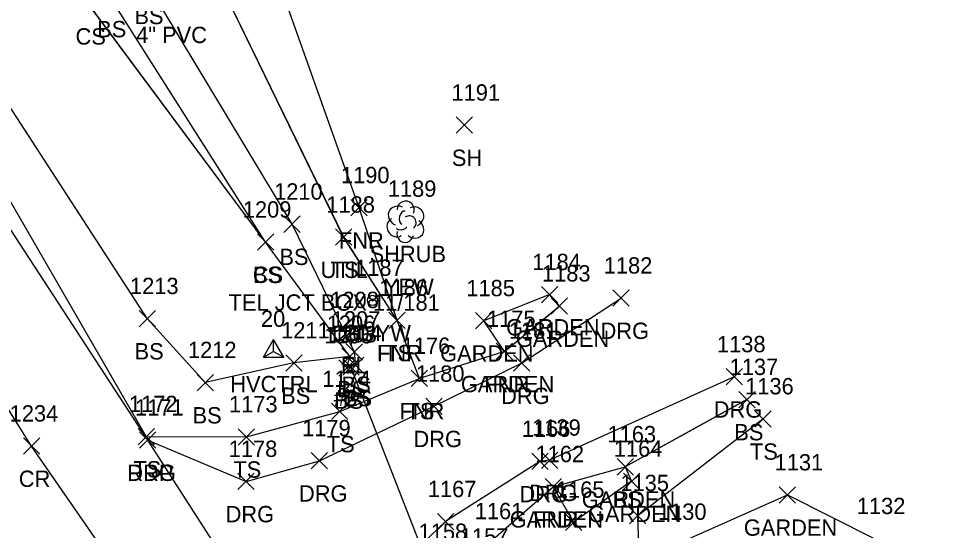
# Model space of a CAD drawing. Extents: x 1415642 to 1422021, y 544543 to 547232.
# Drawn here: x 1416447 to 1416560.6, y 546484.6 to 546547.3 of the extents above; entities that cross this region are included whole.
import ezdxf

# ---------------------------------------------------------------- set-up
doc = ezdxf.new("R2010")
doc.units = 0
for name, color, linetype in [('C_A', 7, 'Continuous'), ('C_I', 7, 'Continuous'), ('CPSM', 7, 'Continuous'), ('D_A', 7, 'Continuous'), ('D_C', 7, 'Continuous'), ('D_I', 7, 'Continuous'), ('D_TIC', 7, 'Continuous'), ('DCP', 7, 'Continuous'), ('L_A', 7, 'Continuous'), ('L_C', 7, 'Continuous'), ('L_I', 7, 'Continuous'), ('L_TIC', 7, 'Continuous'), ('LAPB', 7, 'Continuous'), ('LELB', 7, 'Continuous'), ('LFNC', 7, 'Continuous'), ('LSH', 7, 'Continuous'), ('P_A', 7, 'Continuous'), ('P_I', 7, 'Continuous'), ('P_TIC', 7, 'Continuous'), ('PET', 7, 'Continuous'), ('PRC', 7, 'Continuous'), ('R_A', 7, 'Continuous'), ('R_I', 7, 'Continuous'), ('R_TIC', 7, 'Continuous'), ('RDG', 7, 'Continuous'), ('U_A', 7, 'Continuous'), ('U_C', 7, 'Continuous'), ('U_I', 7, 'Continuous'), ('UDEFAULT', 7, 'Continuous'), ('UEPT', 7, 'Continuous'), ('UPGW', 7, 'Continuous')]:
    doc.layers.add(name, color=color, linetype=linetype)

msp = doc.modelspace()

# ---------------------------------------------------------------- linework, layer by layer
at = {"layer": 'CPSM'}
for p, q in [((1416476.98, 546505.82), (1416478.23, 546507.98)), ((1416479.48, 546505.82), (1416478.23, 546507.98)), ((1416478.23, 546506.54), (1416478.23, 546507.98)), ((1416476.98, 546505.82), (1416478.23, 546506.54)), ((1416478.23, 546506.54), (1416478.23, 546506.54)), ((1416478.23, 546506.54), (1416479.48, 546505.82)), ((1416476.98, 546505.82), (1416479.48, 546505.82))]:
    msp.add_line(p, q, dxfattribs=at)
at = {"layer": 'D_TIC'}
for points in [[(1416486.7, 546503.64), (1416488.7, 546505.64)], [(1416488.7, 546503.64), (1416486.7, 546505.64)]]:
    msp.add_lwpolyline(points, dxfattribs=at)
at = {"layer": 'DCP'}
msp.add_lwpolyline([(1416498.95, 546475.82), (1416487.7, 546504.64)], dxfattribs=at)
msp.add_lwpolyline([(1416498.95, 546475.82), (1416487.7, 546504.64)], dxfattribs=at)
at = {"layer": 'L_TIC'}
for points in [[(1416500.58, 546533.23), (1416502.58, 546535.23)], [(1416502.58, 546533.23), (1416500.58, 546535.23)], [(1416487.7, 546523.12), (1416489.7, 546525.12)], [(1416489.7, 546523.12), (1416487.7, 546525.12)], [(1416479.5, 546521.11), (1416481.5, 546523.11)], [(1416481.5, 546521.11), (1416479.5, 546523.11)], [(1416485.81, 546519.52), (1416487.81, 546521.52)], [(1416487.81, 546519.52), (1416485.81, 546521.52)], [(1416476.24, 546518.91), (1416478.24, 546520.91)], [(1416478.24, 546518.91), (1416476.24, 546520.91)], [(1416476.24, 546518.91), (1416478.24, 546520.91)], [(1416478.24, 546518.91), (1416476.24, 546520.91)], [(1416511.04, 546512.49), (1416513.04, 546514.49)], [(1416513.04, 546512.49), (1416511.04, 546514.49)], [(1416512.23, 546511.09), (1416514.23, 546513.09)], [(1416514.23, 546511.09), (1416512.23, 546513.09)], [(1416461.76, 546509.55), (1416463.76, 546511.55)], [(1416463.76, 546509.55), (1416461.76, 546511.55)], [(1416492.36, 546509.33), (1416494.36, 546511.33)], [(1416494.36, 546509.33), (1416492.36, 546511.33)], [(1416492.36, 546509.33), (1416494.36, 546511.33)], [(1416494.36, 546509.33), (1416492.36, 546511.33)], [(1416502.97, 546509.29), (1416504.97, 546511.29)], [(1416504.97, 546509.29), (1416502.97, 546511.29)], [(1416502.97, 546509.29), (1416504.97, 546511.29)], [(1416504.97, 546509.29), (1416502.97, 546511.29)], [(1416486.57, 546504.93), (1416488.57, 546506.93)], [(1416488.57, 546504.93), (1416486.57, 546506.93)], [(1416486.57, 546504.93), (1416488.57, 546506.93)], [(1416488.57, 546504.93), (1416486.57, 546506.93)], [(1416487.12, 546505.46), (1416489.12, 546507.46)], [(1416489.12, 546505.46), (1416487.12, 546507.46)], [(1416505.5, 546505.54), (1416507.5, 546507.54)], [(1416507.5, 546505.54), (1416505.5, 546507.54)], [(1416505.5, 546505.54), (1416507.5, 546507.54)], [(1416507.5, 546505.54), (1416505.5, 546507.54)], [(1416505.5, 546505.54), (1416507.5, 546507.54)], [(1416507.5, 546505.54), (1416505.5, 546507.54)], [(1416479.71, 546504.12), (1416481.71, 546506.12)], [(1416481.71, 546504.12), (1416479.71, 546506.12)], [(1416486.21, 546503.52), (1416488.21, 546505.52)], [(1416488.21, 546503.52), (1416486.21, 546505.52)], [(1416487.29, 546503.83), (1416489.29, 546505.83)], [(1416489.29, 546503.83), (1416487.29, 546505.83)], [(1416487.29, 546503.83), (1416489.29, 546505.83)], [(1416489.29, 546503.83), (1416487.29, 546505.83)], [(1416495.1, 546502.23), (1416497.1, 546504.23)], [(1416497.1, 546502.23), (1416495.1, 546504.23)], [(1416495.1, 546502.23), (1416497.1, 546504.23)], [(1416497.1, 546502.23), (1416495.1, 546504.23)], [(1416468.86, 546501.72), (1416470.86, 546503.72)], [(1416470.86, 546501.72), (1416468.86, 546503.72)], [(1416535.22, 546499.65), (1416537.22, 546501.65)], [(1416537.22, 546499.65), (1416535.22, 546501.65)], [(1416485.33, 546498.19), (1416487.33, 546500.19)], [(1416487.33, 546498.19), (1416485.33, 546500.19)], [(1416537.17, 546497.28), (1416539.17, 546499.28)], [(1416539.17, 546497.28), (1416537.17, 546499.28)], [(1416461.64, 546495.11), (1416463.64, 546497.11)], [(1416463.64, 546495.11), (1416461.64, 546497.11)], [(1416461.64, 546495.11), (1416463.64, 546497.11)], [(1416463.64, 546495.11), (1416461.64, 546497.11)], [(1416473.89, 546495.08), (1416475.89, 546497.08)], [(1416475.89, 546495.08), (1416473.89, 546497.08)], [(1416520.31, 546491.41), (1416522.31, 546493.41)], [(1416522.31, 546491.41), (1416520.31, 546493.41)], [(1416520.31, 546491.41), (1416522.31, 546493.41)], [(1416522.31, 546491.41), (1416520.31, 546493.41)], [(1416511.48, 546488.98), (1416513.48, 546490.98)], [(1416513.48, 546488.98), (1416511.48, 546490.98)], [(1416511.48, 546488.98), (1416513.48, 546490.98)], [(1416513.48, 546488.98), (1416511.48, 546490.98)], [(1416511.48, 546488.98), (1416513.48, 546490.98)], [(1416513.48, 546488.98), (1416511.48, 546490.98)], [(1416521.07, 546489.64), (1416523.07, 546491.64)], [(1416523.07, 546489.64), (1416521.07, 546491.64)], [(1416540.16, 546487.97), (1416542.16, 546489.97)], [(1416542.16, 546487.97), (1416540.16, 546489.97)], [(1416521.83, 546485.44), (1416523.83, 546487.44)], [(1416523.83, 546485.44), (1416521.83, 546487.44)], [(1416513.98, 546484.63), (1416515.98, 546486.63)], [(1416515.98, 546484.63), (1416513.98, 546486.63)], [(1416513.98, 546484.63), (1416515.98, 546486.63)], [(1416515.98, 546484.63), (1416513.98, 546486.63)]]:
    msp.add_lwpolyline(points, dxfattribs=at)
at = {"layer": 'LAPB'}
for points in [[(1416506.5, 546506.54), (1416513.23, 546512.09), (1416512.04, 546513.49), (1416503.97, 546510.29)], [(1416506.5, 546506.54), (1416513.22, 546512.09), (1416512.04, 546513.49), (1416503.97, 546510.29)], [(1416506.5, 546506.54), (1416503.97, 546510.29)], [(1416506.5, 546506.54), (1416503.97, 546510.29)], [(1416512.48, 546489.98), (1416521.31, 546492.41), (1416522.07, 546490.64), (1416514.98, 546485.63)], [(1416512.48, 546489.98), (1416521.31, 546492.41), (1416522.07, 546490.65), (1416514.98, 546485.63)], [(1416512.48, 546489.98), (1416514.98, 546485.63)], [(1416512.48, 546489.98), (1416514.98, 546485.63)], [(1416543.7, 546466.42), (1416530.22, 546473.8), (1416527.52, 546482.92), (1416541.16, 546488.97), (1416551.79, 546483.62)], [(1416543.71, 546466.42), (1416530.22, 546473.8), (1416527.52, 546482.91), (1416541.17, 546488.97), (1416551.8, 546483.62)]]:
    msp.add_lwpolyline(points, dxfattribs=at)
at = {"layer": 'LELB'}
for points in [[(1416487.57, 546505.93), (1416480.71, 546505.12), (1416469.86, 546502.72), (1416462.76, 546510.55), (1416442.83, 546541.19), (1416430.44, 546560.72), (1416424.35, 546585.18), (1416398.34, 546624.28), (1416389.66, 546643.26), (1416377.3, 546653.03), (1416344.54, 546704.05), (1416343.42, 546724.77), (1416329.35, 546768.04), (1416303.68, 546799.52), (1416274.8, 546819.39), (1416239.26, 546839.41), (1416210.61, 546845.46), (1416203.47, 546849.21), (1416195, 546854.49)], [(1416487.57, 546505.93), (1416480.71, 546505.12), (1416469.86, 546502.72), (1416462.76, 546510.55), (1416442.83, 546541.19), (1416430.44, 546560.72), (1416424.35, 546585.18), (1416398.34, 546624.28), (1416389.66, 546643.27), (1416377.3, 546653.03), (1416344.54, 546704.05), (1416343.42, 546724.76), (1416329.35, 546768.04), (1416303.68, 546799.52), (1416274.8, 546819.4), (1416239.26, 546839.41), (1416210.61, 546845.46), (1416203.48, 546849.21), (1416195, 546854.49)], [(1416488.29, 546504.83), (1416488.12, 546506.46), (1416480.5, 546522.11), (1416462.74, 546551.59), (1416447.84, 546594.51), (1416422.44, 546641.16), (1416410.18, 546676.27), (1416393.07, 546713.79), (1416378.8, 546749.63), (1416367.97, 546783.97), (1416347.35, 546811.63), (1416340.26, 546839.45), (1416338.76, 546849.28)], [(1416488.29, 546504.83), (1416488.12, 546506.46), (1416480.5, 546522.11), (1416462.74, 546551.59), (1416447.84, 546594.51), (1416422.44, 546641.16), (1416410.17, 546676.27), (1416393.07, 546713.79), (1416378.8, 546749.63), (1416367.97, 546783.97), (1416347.34, 546811.63), (1416340.26, 546839.45), (1416338.76, 546849.28)], [(1416462.64, 546496.11), (1416437.87, 546538.89), (1416411.19, 546576.82), (1416382.17, 546614.17), (1416360.8, 546639.39), (1416323.65, 546683.15), (1416301.53, 546707.03), (1416273.6, 546735.69), (1416258.67, 546751.22), (1416224.41, 546784.74), (1416201.13, 546806.07), (1416169.09, 546832.26)], [(1416462.64, 546496.11), (1416437.87, 546538.89), (1416411.18, 546576.82), (1416382.17, 546614.17), (1416360.8, 546639.39), (1416323.65, 546683.15), (1416301.53, 546707.03), (1416273.6, 546735.69), (1416258.67, 546751.22), (1416224.4, 546784.74), (1416201.13, 546806.07), (1416169.09, 546832.26)], [(1416488.29, 546504.83), (1416487.21, 546504.52), (1416487.57, 546505.93), (1416477.24, 546519.91), (1416458.18, 546549.98), (1416444.98, 546593.05), (1416421.02, 546640.5), (1416406.73, 546674.57), (1416393.07, 546713.79)], [(1416488.29, 546504.83), (1416487.21, 546504.52), (1416487.57, 546505.93), (1416477.24, 546519.91), (1416458.18, 546549.99), (1416444.98, 546593.04), (1416421.01, 546640.5), (1416406.73, 546674.57), (1416393.07, 546713.79)], [(1416493.36, 546510.33), (1416486.81, 546520.52), (1416469.71, 546555.6), (1416453.47, 546601.16)], [(1416493.36, 546510.33), (1416486.82, 546520.52), (1416469.71, 546555.59), (1416453.47, 546601.16)], [(1416477.24, 546519.91), (1416455.53, 546549.09), (1416441.96, 546593.48)], [(1416477.24, 546519.91), (1416455.53, 546549.1), (1416441.96, 546593.48)], [(1416462.64, 546496.11), (1416474.89, 546496.08), (1416486.33, 546499.19), (1416496.1, 546503.23)], [(1416462.64, 546496.11), (1416474.89, 546496.08), (1416486.33, 546499.19), (1416496.1, 546503.23)], [(1416536.22, 546500.65), (1416521.31, 546492.41)], [(1416536.21, 546500.65), (1416521.31, 546492.41)], [(1416523.32, 546471.61), (1416522.83, 546486.44), (1416538.17, 546498.28)], [(1416523.32, 546471.61), (1416522.83, 546486.44), (1416538.17, 546498.28)]]:
    msp.add_lwpolyline(points, dxfattribs=at)
at = {"layer": 'LFNC'}
for points in [[(1416506.5, 546506.54), (1416496.1, 546503.23), (1416493.36, 546510.33), (1416488.7, 546524.12), (1416477.63, 546555.25), (1416468.51, 546581.39), (1416458.21, 546611.19), (1416444.47, 546650.39), (1416432.95, 546683.5)], [(1416506.5, 546506.54), (1416496.1, 546503.23), (1416493.36, 546510.33), (1416488.7, 546524.12), (1416477.63, 546555.24), (1416468.51, 546581.39), (1416458.21, 546611.19), (1416444.47, 546650.39), (1416432.95, 546683.5)], [(1416616.17, 546291.53), (1416602.64, 546290.41), (1416594.37, 546289.3), (1416578.97, 546322.54), (1416563.77, 546356.27), (1416548.95, 546386.35), (1416547.3, 546389.95), (1416530.29, 546426.68), (1416513.55, 546462.2), (1416508.34, 546472.94), (1416504.48, 546483), (1416512.48, 546489.98)], [(1416616.17, 546291.53), (1416602.64, 546290.41), (1416594.37, 546289.3), (1416578.97, 546322.54), (1416563.77, 546356.27), (1416548.95, 546386.35), (1416547.3, 546389.95), (1416530.29, 546426.68), (1416513.55, 546462.2), (1416508.35, 546472.93), (1416504.48, 546483), (1416512.48, 546489.98)]]:
    msp.add_lwpolyline(points, dxfattribs=at)
at = {"layer": 'LSH'}
msp.add_line((1416494.36, 546522.46), (1416494.36, 546522.46), dxfattribs=at)
msp.add_line((1416494.36, 546522.46), (1416494.36, 546522.46), dxfattribs=at)
msp.add_arc((1416494.4, 546523.89), 1.05, 335.5272, 180.9563, dxfattribs=at)
for centre, major_axis, ratio, start_param, end_param in [((1416493.57, 546523.12), (1.21, -0.51), 0.895232, 1.570796, 4.712389), ((1416494.15, 546522.91), (-0.208, -0.792), 0.645439, 3.141593, 6.283185), ((1416495.4, 546523.04), (-1.14, -0.48), 0.949671, 1.570796, 4.712389), ((1416493.27, 546521.75), (0.58, -1.04), 0.959034, 3.141593, 6.283185), ((1416494.86, 546522.29), (-0.5, 0.667), 0.989748, 3.141593, 6.283185), ((1416495.36, 546521.62), (-1.09, 0.79), 0.841452, 1.570796, 4.712389), ((1416493.9, 546521.71), (-0.625, -0.083), 0.423636, 0, 3.141593), ((1416494.36, 546520.96), (0.26, 1.06), 0.942809, 1.570796, 4.712389)]:
    msp.add_ellipse(centre, major_axis=major_axis, ratio=ratio, start_param=start_param, end_param=end_param, dxfattribs=at)
at = {"layer": 'P_TIC'}
for points in [[(1416461.82, 546494.68), (1416463.82, 546496.68)], [(1416463.82, 546494.68), (1416461.82, 546496.68)], [(1416447.59, 546493.95), (1416449.59, 546495.95)], [(1416449.59, 546493.95), (1416447.59, 546495.95)]]:
    msp.add_lwpolyline(points, dxfattribs=at)
at = {"layer": 'PET'}
for points in [[(1416619.56, 546186.67), (1416601.63, 546226.16), (1416579.47, 546277.45), (1416562.03, 546315.23), (1416547.08, 546347.32), (1416527.73, 546384.04), (1416509.97, 546418.47), (1416487.43, 546457.37), (1416462.82, 546495.68), (1416435.56, 546537.44), (1416408.53, 546574.62)], [(1416619.56, 546186.67), (1416601.62, 546226.16), (1416579.47, 546277.45), (1416562.03, 546315.23), (1416547.08, 546347.32), (1416527.73, 546384.03), (1416509.97, 546418.46), (1416487.43, 546457.37), (1416462.82, 546495.68), (1416435.56, 546537.44), (1416408.53, 546574.61)]]:
    msp.add_lwpolyline(points, dxfattribs=at)
at = {"layer": 'PRC'}
for points in [[(1416610.25, 546183.67), (1416586.12, 546227.19), (1416567.64, 546274.51), (1416551.19, 546309.95), (1416536.28, 546342.88), (1416517.21, 546379.83), (1416500.09, 546412.89), (1416469.99, 546464.05), (1416448.59, 546494.95), (1416427.64, 546528.31), (1416425.29, 546532.23), (1416399.16, 546568.17)], [(1416610.26, 546183.67), (1416586.11, 546227.19), (1416567.64, 546274.51), (1416551.18, 546309.96), (1416536.27, 546342.88), (1416517.21, 546379.83), (1416500.09, 546412.89), (1416469.99, 546464.05), (1416448.59, 546494.95), (1416427.64, 546528.31), (1416425.29, 546532.24), (1416399.16, 546568.17)]]:
    msp.add_lwpolyline(points, dxfattribs=at)
at = {"layer": 'R_TIC'}
for points in [[(1416519.79, 546512.06), (1416521.79, 546514.06)], [(1416521.79, 546512.06), (1416519.79, 546514.06)], [(1416507.61, 546504.1), (1416509.61, 546506.1)], [(1416509.61, 546504.1), (1416507.61, 546506.1)], [(1416533.66, 546502.43), (1416535.66, 546504.43)], [(1416535.66, 546502.43), (1416533.66, 546504.43)], [(1416496.87, 546498.82), (1416498.87, 546500.82)], [(1416498.87, 546498.82), (1416496.87, 546500.82)], [(1416461.82, 546494.68), (1416463.82, 546496.68)], [(1416463.82, 546494.68), (1416461.82, 546496.68)], [(1416482.85, 546492.15), (1416484.85, 546494.15)], [(1416484.85, 546492.15), (1416482.85, 546494.15)], [(1416509.86, 546492.07), (1416511.86, 546494.07)], [(1416511.86, 546492.07), (1416509.86, 546494.07)], [(1416511.03, 546492.22), (1416513.03, 546494.22)], [(1416513.03, 546492.22), (1416511.03, 546494.22)], [(1416473.86, 546489.62), (1416475.86, 546491.62)], [(1416475.86, 546489.62), (1416473.86, 546491.62)], [(1416498.29, 546484.7), (1416500.29, 546486.7)], [(1416500.29, 546484.7), (1416498.29, 546486.7)]]:
    msp.add_lwpolyline(points, dxfattribs=at)
at = {"layer": 'RDG'}
for points in [[(1416462.82, 546495.68), (1416474.86, 546490.62), (1416483.85, 546493.15), (1416497.87, 546499.82), (1416508.61, 546505.1), (1416520.79, 546513.06)], [(1416462.82, 546495.68), (1416474.86, 546490.62), (1416483.85, 546493.15), (1416497.87, 546499.82), (1416508.61, 546505.1), (1416520.79, 546513.06)], [(1416534.66, 546503.43), (1416512.03, 546493.22), (1416510.86, 546493.07), (1416499.29, 546485.7), (1416491.99, 546478.75), (1416486.93, 546468.76), (1416487.43, 546457.37)], [(1416534.66, 546503.43), (1416512.03, 546493.22), (1416510.86, 546493.07), (1416499.29, 546485.71), (1416491.99, 546478.75), (1416486.93, 546468.76), (1416487.43, 546457.37)]]:
    msp.add_lwpolyline(points, dxfattribs=at)
at = {"layer": 'UDEFAULT'}
for points in [[(1416485.81, 546519.52), (1416487.81, 546521.52)], [(1416487.81, 546519.52), (1416485.81, 546521.52)]]:
    msp.add_lwpolyline(points, dxfattribs=at)
at = {"layer": 'UEPT'}
for p, q in [((1416488.11, 546510.5), (1416487.94, 546509.67)), ((1416487.11, 546508), (1416487.11, 546509.67)), ((1416487.11, 546509.67), (1416488.78, 546509.67)), ((1416487.94, 546508.84), (1416487.94, 546508.84)), ((1416488.78, 546509.67), (1416488.78, 546508)), ((1416488.78, 546508), (1416487.11, 546508)), ((1416487.69, 546507.17), (1416487.94, 546508))]:
    msp.add_line(p, q, dxfattribs=at)
at = {"layer": 'UPGW'}
for radius in [0.625, 0.0833]:
    msp.add_circle((1416490.34, 546512.78), radius, dxfattribs=at)

# ---------------------------------------------------------------- texts
at = {"layer": 'C_A'}
msp.add_text('HVCTRL', height=2, dxfattribs=at).set_placement((1416472.92, 546501.54))
at = {"layer": 'C_I'}
msp.add_text('20', height=2, dxfattribs=at).set_placement((1416476.68, 546509.54))
at = {"layer": 'D_A'}
msp.add_text('P', height=2, dxfattribs=at).set_placement((1416487.08, 546499.64))
at = {"layer": 'D_C'}
msp.add_text('4" PVC', height=2, dxfattribs=at).set_placement((1416461.39, 546544.27))
at = {"layer": 'D_I'}
msp.add_text('1203', height=2, dxfattribs=at).set_placement((1416484.93, 546507.64))
at = {"layer": 'L_A'}
for s, p in [('BS', (1416461.18, 546546.59)), ('BS', (1416456.62, 546544.98)), ('CS', (1416453.97, 546544.09)), ('SH', (1416500.06, 546529.23)), ('FNR', (1416486.23, 546519.12)), ('BS', (1416478.94, 546517.11)), ('SHRUB', (1416489.99, 546517.46)), ('CS', (1416475.68, 546514.91)), ('BS', (1416475.68, 546514.91)), ('TS', (1416485.22, 546515.52)), ('GARDEN', (1416506.71, 546508.49)), ('GARDEN', (1416507.9, 546507.09)), ('BS', (1416461.2, 546505.55)), ('FNR', (1416490.9, 546505.33)), ('TS', (1416491.77, 546505.33)), ('GARDEN', (1416498.63, 546505.29)), ('GARDEN', (1416498.63, 546505.29)), ('BS', (1416486.56, 546501.46)), ('GARDEN', (1416501.17, 546501.54)), ('GARDEN', (1416501.17, 546501.54)), ('FNR', (1416504.04, 546501.54)), ('BS', (1416479.15, 546500.12)), ('BS', (1416486.01, 546500.93)), ('BS', (1416486.01, 546500.93)), ('BS', (1416485.65, 546499.52)), ('BS', (1416486.73, 546499.83)), ('BS', (1416486.73, 546499.83)), ('BS', (1416468.3, 546497.72)), ('FNR', (1416493.64, 546498.23)), ('TS', (1416494.51, 546498.23)), ('BS', (1416534.66, 546495.65)), ('TS', (1416484.74, 546494.19)), ('TS', (1416536.58, 546493.28)), ('TS', (1416461.05, 546491.11)), ('TS', (1416461.05, 546491.11)), ('TS', (1416473.3, 546491.08)), ('GARDEN', (1416515.98, 546487.41)), ('BS', (1416519.75, 546487.41)), ('GARDEN', (1416516.74, 546485.64)), ('GARDEN', (1416507.15, 546484.98)), ('GARDEN', (1416507.15, 546484.98)), ('FNR', (1416510.02, 546484.98)), ('GARDEN', (1416535.83, 546483.97))]:
    msp.add_text(s, height=2, dxfattribs=at).set_placement(p)
at = {"layer": 'L_C'}
msp.add_text('YEW', height=2, dxfattribs=at).set_placement((1416491.76, 546513.46))
at = {"layer": 'L_I'}
for s, p in [('1191', (1416500.02, 546537.23)), ('1190', (1416486.48, 546527.12)), ('1210', (1416478.29, 546525.11)), ('1189', (1416492.22, 546525.46)), ('1209', (1416474.46, 546522.91)), ('1209', (1416474.46, 546522.91)), ('1188', (1416484.69, 546523.52)), ('1184', (1416509.92, 546516.49)), ('1183', (1416511.1, 546515.09)), ('1213', (1416460.64, 546513.55)), ('1186', (1416491.18, 546513.33)), ('1186', (1416491.18, 546513.33)), ('1185', (1416501.84, 546513.29)), ('1185', (1416501.84, 546513.29)), ('1207', (1416485.35, 546509.46)), ('1175', (1416504.37, 546509.54)), ('1175', (1416504.37, 546509.54)), ('1175', (1416504.37, 546509.54)), ('1211', (1416479.15, 546508.12)), ('1206', (1416484.74, 546508.93)), ('1206', (1416484.74, 546508.93)), ('1204', (1416485.51, 546507.83)), ('1204', (1416485.51, 546507.83)), ('1205', (1416484.44, 546507.52)), ('1212', (1416467.74, 546505.72)), ('1176', (1416493.92, 546506.23)), ('1176', (1416493.92, 546506.23)), ('1137', (1416534.09, 546503.65)), ('1174', (1416484.2, 546502.19)), ('1136', (1416535.99, 546501.28)), ('1172', (1416460.51, 546499.11)), ('1172', (1416460.51, 546499.11)), ('1173', (1416472.77, 546499.08)), ('1163', (1416519.13, 546495.41)), ('1163', (1416519.13, 546495.41)), ('1164', (1416519.9, 546493.64)), ('1162', (1416510.31, 546492.98)), ('1162', (1416510.31, 546492.98)), ('1162', (1416510.31, 546492.98)), ('1131', (1416539.6, 546491.97)), ('1165', (1416512.81, 546488.63)), ('1165', (1416512.81, 546488.63)), ('1135', (1416520.71, 546489.44)), ('1132', (1416549.67, 546486.62)), ('1132', (1416549.67, 546486.62)), ('1161', (1416502.87, 546486)), ('1130', (1416525.31, 546485.92)), ('1158', (1416495.99, 546483.46)), ('1157', (1416501.04, 546482.89))]:
    msp.add_text(s, height=2, dxfattribs=at).set_placement(p)
at = {"layer": 'P_A'}
for s, p in [('CR', (1416447.02, 546489.95)), ('RDP', (1416460.31, 546490.68))]:
    msp.add_text(s, height=2, dxfattribs=at).set_placement(p)
at = {"layer": 'P_I'}
for s, p in [('1234', (1416445.9, 546497.95)), ('1171', (1416461.26, 546498.68))]:
    msp.add_text(s, height=2, dxfattribs=at).set_placement(p)
at = {"layer": 'R_A'}
for p in [(1416518.28, 546508.06), (1416506.1, 546500.1), (1416532.15, 546498.43), (1416495.36, 546494.82), (1416460.31, 546490.68), (1416481.34, 546488.15), (1416508.35, 546488.07), (1416509.52, 546488.22), (1416472.35, 546485.62)]:
    msp.add_text('DRG', height=2, dxfattribs=at).set_placement(p)
at = {"layer": 'R_I'}
for s, p in [('1182', (1416518.67, 546516.06)), ('1181', (1416507.05, 546508.1)), ('1138', (1416532.54, 546506.43)), ('1180', (1416495.66, 546502.82)), ('1171', (1416461.26, 546498.68)), ('1179', (1416481.72, 546496.15)), ('1166', (1416508.63, 546496.07)), ('1139', (1416509.9, 546496.22)), ('1178', (1416472.73, 546493.62)), ('1167', (1416497.12, 546488.7))]:
    msp.add_text(s, height=2, dxfattribs=at).set_placement(p)
at = {"layer": 'U_A'}
for s, p in [('UTIL', (1416483.98, 546515.52)), ('GUYW', (1416486.73, 546507.78)), ('EL', (1416486.48, 546503.84))]:
    msp.add_text(s, height=2, dxfattribs=at).set_placement(p)
at = {"layer": 'U_C'}
for s, p in [('TEL JCT BOX 11/181', (1416472.72, 546511.52)), ('#25', (1416485.58, 546499.84))]:
    msp.add_text(s, height=2, dxfattribs=at).set_placement(p)
at = {"layer": 'U_I'}
for s, p in [('1188', (1416484.69, 546523.52)), ('1187', (1416488.21, 546515.78)), ('1208', (1416485.17, 546511.84))]:
    msp.add_text(s, height=2, dxfattribs=at).set_placement(p)

doc.saveas('drawing.dxf')
